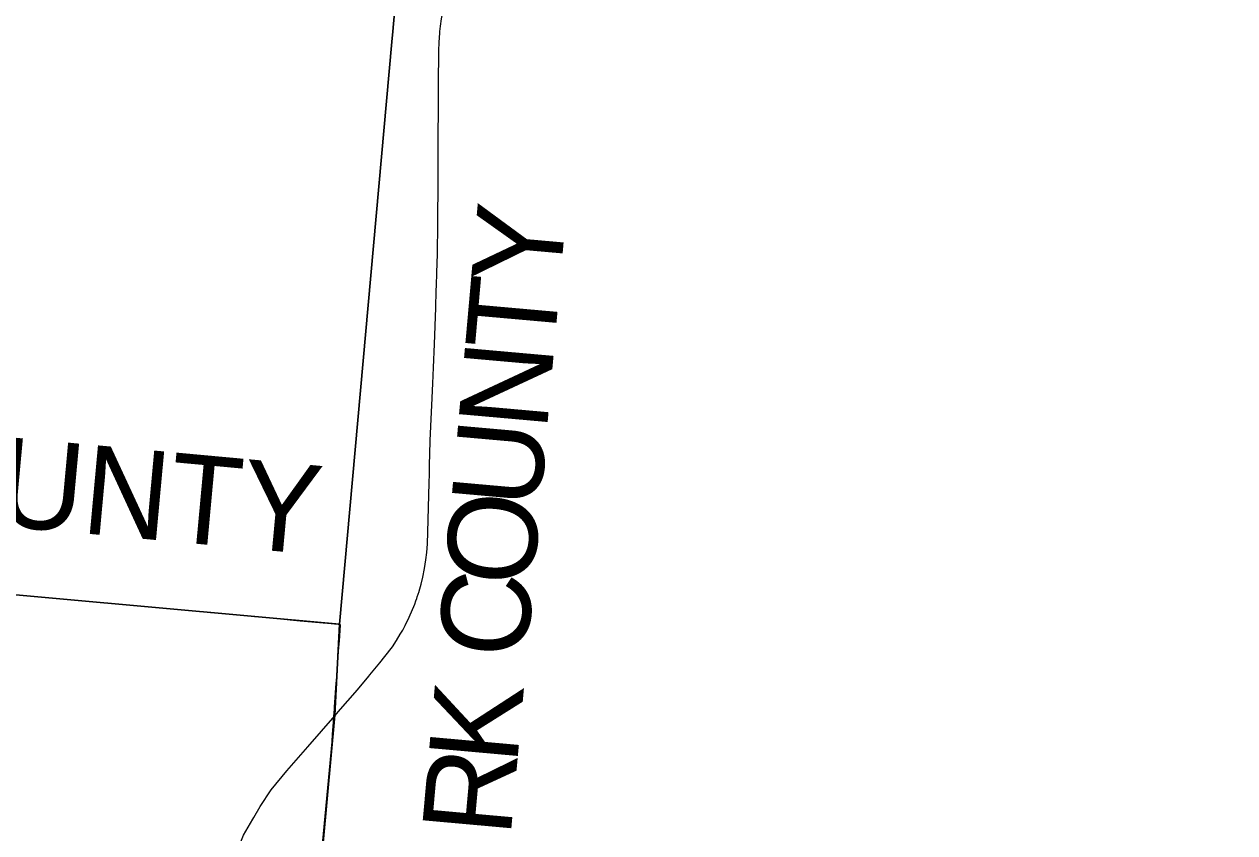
# Model space of a CAD drawing. Extents: x 0 to 34, y 0 to 22.
# Drawn here: x 5.8916 to 6.1103, y 15.8236 to 15.9697 of the extents above; entities that cross this region are included whole.
import ezdxf

# ---------------------------------------------------------------- set-up
doc = ezdxf.new("R2010")
doc.units = 0
for name, color, linetype in [('GM_X_Corporation', 7, 'Continuous'), ('GM_X_County', 7, 'Continuous'), ('GM_X_County_Text', 7, 'Continuous'), ('GM_X_State_Route', 7, 'Continuous')]:
    doc.layers.add(name, color=color, linetype=linetype)

msp = doc.modelspace()

# ---------------------------------------------------------------- linework, layer by layer
at = {"layer": 'GM_X_Corporation'}
msp.add_lwpolyline([(5.88879, 15.86676), (5.89511, 15.86617), (5.89832, 15.86587), (5.89839, 15.86586), (5.90264, 15.86548), (5.90272, 15.86547), (5.90632, 15.86514), (5.91, 15.8648), (5.91007, 15.8648), (5.91378, 15.86445), (5.91385, 15.86445), (5.91758, 15.8641), (5.91765, 15.8641), (5.92141, 15.86375), (5.92148, 15.86374), (5.92527, 15.86339), (5.92533, 15.86339), (5.92888, 15.86306), (5.92895, 15.86305), (5.93323, 15.86265), (5.93328, 15.86265), (5.93731, 15.86228), (5.93735, 15.86227), (5.94145, 15.86189), (5.94146, 15.86189), (5.94566, 15.8615), (5.94577, 15.86149), (5.94836, 15.86125), (5.94872, 15.86122), (5.94872, 15.86114), (5.94857, 15.85916), (5.94856, 15.85905), (5.94846, 15.85759), (5.94842, 15.85708), (5.94813, 15.85305), (5.94797, 15.85087), (5.94795, 15.85067), (5.94795, 15.85061), (5.94763, 15.84626), (5.94762, 15.84601), (5.94761, 15.84592), (5.94746, 15.84393), (5.94744, 15.8436), (5.94744, 15.84353), (5.94728, 15.84136), (5.94718, 15.84003), (5.94515, 15.81823)], dxfattribs=at)
at = {"layer": 'GM_X_County'}
for points in [[(5.96338, 16.02723), (5.95819, 15.9684), (5.95806, 15.96651), (5.94861, 15.86127), (5.88136, 15.86734)], [(6.38664, 15.64699), (6.23464, 15.6613), (6.22299, 15.6624), (6.20568, 15.66403), (6.20475, 15.66412), (6.203, 15.66429), (6.20174, 15.66442), (6.19303, 15.66523), (6.06869, 15.67697), (6.01115, 15.68301), (5.93347, 15.69052), (5.93581, 15.717), (5.94104, 15.77103), (5.9414, 15.77479), (5.94148, 15.77547), (5.9416, 15.77679), (5.94215, 15.78365), (5.94776, 15.8448), (5.94861, 15.86127), (5.95806, 15.96651), (5.95819, 15.9684), (5.96338, 16.02723)], [(5.88136, 15.86734), (5.94861, 15.86127), (5.94776, 15.8448), (5.94215, 15.78365)]]:
    msp.add_lwpolyline(points, dxfattribs=at)
at = {"layer": 'GM_X_State_Route'}
for points in [[(5.96642, 15.9508), (5.96644, 15.95301), (5.96649, 15.95935), (5.96652, 15.96436), (5.96654, 15.96488), (5.96659, 15.96647), (5.9667, 15.96805), (5.96673, 15.96837), (5.96683, 15.96935), (5.96702, 15.97065), (5.96726, 15.97195), (5.9676, 15.97349), (5.96796, 15.97491), (5.96814, 15.97564), (5.96836, 15.97638), (5.96872, 15.97735)], [(5.96496, 15.89435), (5.96496, 15.89443), (5.9652, 15.8996), (5.96533, 15.9021), (5.96538, 15.90352), (5.96542, 15.90474), (5.96549, 15.9062), (5.96556, 15.90764), (5.96572, 15.91187), (5.96597, 15.91846), (5.96606, 15.92158), (5.9661, 15.92247), (5.96619, 15.92475), (5.96627, 15.92818), (5.96632, 15.93359), (5.96633, 15.93426), (5.96638, 15.94086), (5.96639, 15.94297), (5.96639, 15.94419), (5.9664, 15.94482), (5.96642, 15.95063), (5.96642, 15.9508)], [(5.96295, 15.86714), (5.96298, 15.86722), (5.96333, 15.86849), (5.96363, 15.86977), (5.96394, 15.87132), (5.96418, 15.87289), (5.96433, 15.87419), (5.96446, 15.87577), (5.96456, 15.87787), (5.96481, 15.88681), (5.96483, 15.88839), (5.96485, 15.88996), (5.96496, 15.89435)], [(5.96002, 15.8602), (5.96009, 15.86031), (5.96044, 15.86105), (5.96116, 15.86254), (5.96218, 15.86489), (5.96239, 15.86547), (5.96254, 15.8659), (5.96264, 15.86622), (5.96295, 15.86714)], [(5.95407, 15.8521), (5.95586, 15.85425), (5.9579, 15.85685), (5.95813, 15.85718), (5.95885, 15.85829), (5.95953, 15.85943), (5.96002, 15.8602)], [(5.94778, 15.84475), (5.94837, 15.84544), (5.95183, 15.84941), (5.95386, 15.85184), (5.95407, 15.8521)], [(5.93311, 15.82632), (5.93424, 15.82829), (5.93621, 15.83135), (5.93908, 15.83475), (5.94288, 15.83912), (5.94778, 15.84475)], [(5.92919, 15.81794), (5.93122, 15.82311), (5.93294, 15.82603), (5.93311, 15.82632)]]:
    msp.add_lwpolyline(points, dxfattribs=at)

# ---------------------------------------------------------------- texts
at = {"layer": 'GM_X_County_Text'}
for s, height, rotation, p in [('Y', 0.01607, 84.9223, (5.98835, 15.92213)), ('T', 0.01607, 84.9223, (5.98729, 15.91018)), ('N', 0.01607, 84.9223, (5.98603, 15.89604)), ('MIAMI COUNTY', 0.016074, 354.7319, (5.78638, 15.88837)), ('U', 0.01607, 84.9217, (5.98478, 15.88191)), ('O', 0.01607, 84.9156, (5.98352, 15.86778)), ('C', 0.01607, 84.9024, (5.98235, 15.85472)), ('K', 0.01607, 84.8755, (5.98065, 15.83569)), ('R', 0.01607, 84.8606, (5.97947, 15.82263))]:
    msp.add_text(s, height=height, rotation=rotation, dxfattribs=at).set_placement(p)

doc.saveas('drawing.dxf')
